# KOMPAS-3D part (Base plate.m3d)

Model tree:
1. X Axis
2. Y Axis
3. Z Axis
4. Origin  (labels: D:\Program Files\ASCON\KOMPAS-3D V10\Sys\GRAPHIC_EN.LYT; Plate 01)
     Wall Thickness 1 = 1; Wall Thickness 2 = 1; Distance 2 = 10

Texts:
  Plate 01
  Three Point Plane
  Plane at Angle
  Line and Point Plane
  Axis through Two Vertices
  Axis of Feature
  Axis of Conical Surface
  Axis through Edge
  Trim by Surface
  Trim by Sketch
  Feature with No History
  Intersection Axis of Two Planes
  Two Line Plane
  Line and Face Plane
  Bend by line
  Hole in sheet body
  Cut in sheet body
  Point in CM
  Linear Dimension from Line to Point
  Surface Finish Symbol
  Geometric Tolerance Symbol
  Leader #1
  Leader #2
  Leader #3
  Shape Deviations and Datum
  Node point number
  Mark of coordination axis
  Node point designation
  Mark/Reference designation with leader
  Mark/reference designation on line
  Mark/Reference designation without leader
